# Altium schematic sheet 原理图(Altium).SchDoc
size A4
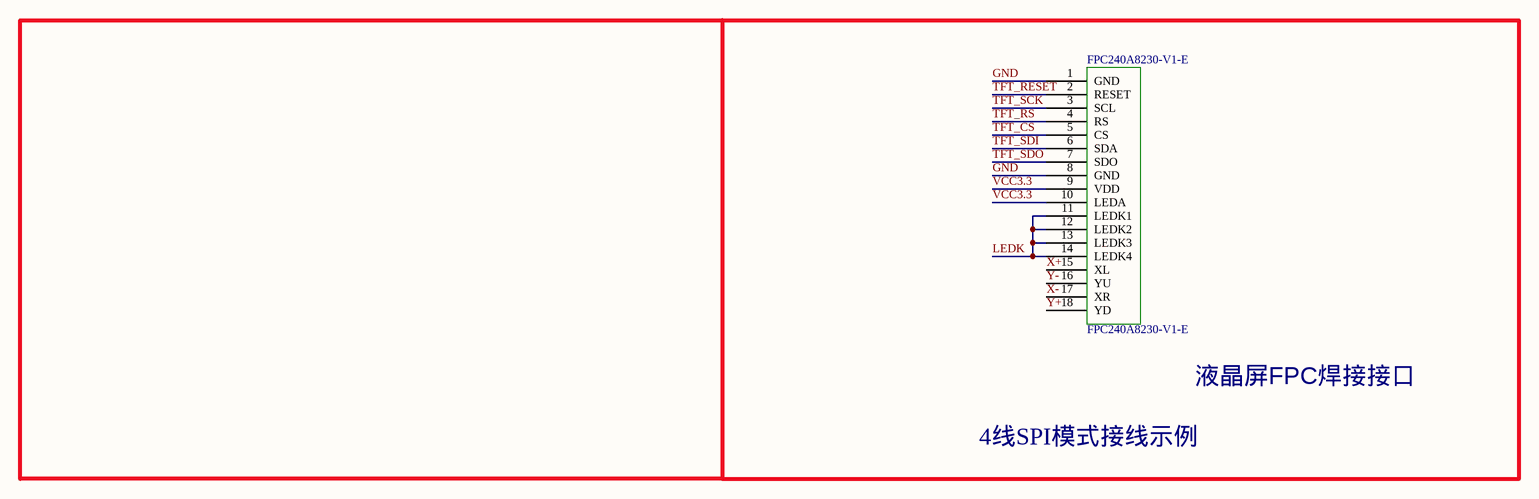
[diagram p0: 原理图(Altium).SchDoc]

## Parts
FPC240A8230-V1-E  FPC240A8230-V1-E  [FPC240A8230-V1-E]

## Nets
GND: FPC240A8230-V1-E.1(GND) FPC240A8230-V1-E.8(GND)
LEDK: FPC240A8230-V1-E.11(LEDK1) FPC240A8230-V1-E.12(LEDK2) FPC240A8230-V1-E.13(LEDK3) FPC240A8230-V1-E.14(LEDK4)
TFT_CS: FPC240A8230-V1-E.5(CS)
TFT_RESET: FPC240A8230-V1-E.2(RESET)
TFT_RS: FPC240A8230-V1-E.4(RS)
TFT_SCK: FPC240A8230-V1-E.3(SCL)
TFT_SDI: FPC240A8230-V1-E.6(SDA)
TFT_SDO: FPC240A8230-V1-E.7(SDO)
VCC3.3: FPC240A8230-V1-E.9(VDD) FPC240A8230-V1-E.10(LEDA)
X+: FPC240A8230-V1-E.15(XL)
X-: FPC240A8230-V1-E.17(XR)
Y+: FPC240A8230-V1-E.18(YD)
Y-: FPC240A8230-V1-E.16(YU)

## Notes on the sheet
- 液晶屏FPC焊接接口
- 4线SPI模式接线示例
